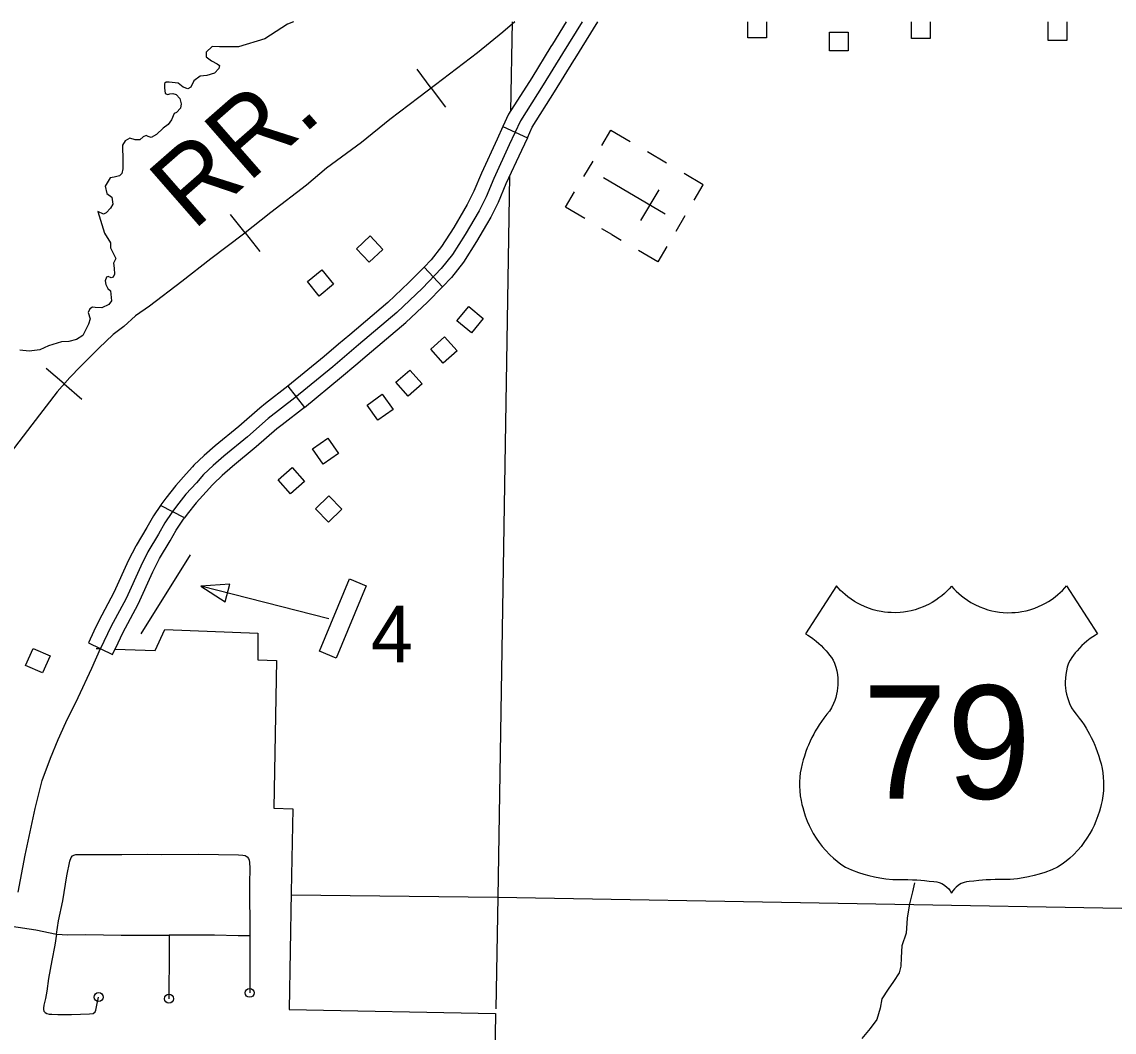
# Model space of a CAD drawing. Extents: x 61396 to 64680, y 55472 to 57605.
# Drawn here: x 62867.8 to 63058.6, y 56508.8 to 56685.3 of the extents above; entities that cross this region are included whole.
import ezdxf

# ---------------------------------------------------------------- set-up
doc = ezdxf.new("R2010")
doc.units = 0
for name, color, linetype in [('22', 7, 'Continuous'), ('31', 7, 'Continuous'), ('33', 7, 'Continuous'), ('35', 7, 'Continuous'), ('4', 7, 'Continuous'), ('40', 7, 'Continuous'), ('5', 7, 'Continuous'), ('56', 7, 'Continuous'), ('57', 7, 'Continuous'), ('6', 7, 'Continuous')]:
    doc.layers.add(name, color=color, linetype=linetype)

msp = doc.modelspace()

# ---------------------------------------------------------------- linework, layer by layer
at = {"layer": '22'}
for points in [[(63030.23, 56586.68), (63029.82, 56586.22), (63029.42, 56585.82), (63028.98, 56585.4), (63028.5, 56584.99), (63028.03, 56584.63), (63027.47, 56584.23), (63026.86, 56583.85), (63026.17, 56583.47), (63025.29, 56583.07), (63024.62, 56582.81), (63023.86, 56582.56), (63023.17, 56582.38), (63022.53, 56582.25), (63021.85, 56582.14), (63021.23, 56582.08), (63020.38, 56582.04), (63019.69, 56582.05), (63019.09, 56582.09), (63018.52, 56582.15), (63017.94, 56582.23), (63017.21, 56582.38), (63016.53, 56582.56), (63015.71, 56582.83), (63015.01, 56583.1), (63014.38, 56583.39), (63013.8, 56583.69), (63013.27, 56584.01), (63012.67, 56584.4), (63012.12, 56584.8), (63011.65, 56585.19), (63011.25, 56585.54), (63010.84, 56585.94), (63010.44, 56586.36), (63010.12, 56586.73), (63004.71, 56578.36), (63005.1, 56578.13), (63005.56, 56577.83), (63005.99, 56577.52), (63006.57, 56577.07), (63007.04, 56576.67), (63007.45, 56576.29), (63007.87, 56575.86), (63008.3, 56575.38), (63008.61, 56575.01), (63008.91, 56574.62), (63009.22, 56574.19), (63009.52, 56573.74), (63009.79, 56573.21), (63010, 56572.55), (63010.16, 56571.91), (63010.28, 56571.22), (63010.35, 56570.58), (63010.37, 56569.96), (63010.35, 56569.38), (63010.32, 56568.91), (63010.24, 56568.34), (63010.13, 56567.81), (63009.98, 56567.23), (63009.82, 56566.72), (63009.6, 56566.15), (63009.24, 56565.41), (63008.88, 56564.83), (63008.45, 56564.31), (63007.92, 56563.63), (63007.49, 56563.03), (63007.09, 56562.44), (63006.72, 56561.85), (63006.41, 56561.33), (63006.14, 56560.84), (63005.84, 56560.25), (63005.51, 56559.57), (63005.21, 56558.9), (63005.01, 56558.41), (63004.77, 56557.77), (63004.51, 56556.99), (63004.3, 56556.34), (63004.1, 56555.64), (63003.92, 56554.81), (63003.8, 56554.08), (63003.72, 56553.32), (63003.67, 56552.49), (63003.66, 56551.71), (63003.7, 56550.94), (63003.79, 56550.05), (63003.93, 56549.2), (63004.07, 56548.55), (63004.22, 56547.99), (63004.4, 56547.35), (63004.65, 56546.55), (63005.01, 56545.59), (63005.32, 56544.88), (63005.67, 56544.15), (63006.06, 56543.44), (63006.57, 56542.62), (63007.1, 56541.86), (63007.61, 56541.2), (63008.19, 56540.53), (63008.94, 56539.75), (63009.57, 56539.17), (63010.22, 56538.62)], [(63030.23, 56586.68), (63030.64, 56586.22), (63031.03, 56585.82), (63031.48, 56585.4), (63031.96, 56584.99), (63032.43, 56584.63), (63032.99, 56584.23), (63033.6, 56583.85), (63034.29, 56583.47), (63035.16, 56583.07), (63035.83, 56582.81), (63036.59, 56582.56), (63037.29, 56582.38), (63037.93, 56582.25), (63038.6, 56582.14), (63039.22, 56582.08), (63040.07, 56582.04), (63040.76, 56582.05), (63041.37, 56582.09), (63041.94, 56582.15), (63042.52, 56582.23), (63043.25, 56582.38), (63043.92, 56582.56), (63044.75, 56582.83), (63045.44, 56583.1), (63046.07, 56583.39), (63046.65, 56583.69), (63047.19, 56584.01), (63047.79, 56584.4), (63048.34, 56584.8), (63048.81, 56585.19), (63049.21, 56585.54), (63049.61, 56585.94), (63050.01, 56586.36), (63050.34, 56586.73), (63055.74, 56578.36), (63055.36, 56578.13), (63054.9, 56577.83), (63054.46, 56577.52), (63053.88, 56577.07), (63053.42, 56576.67), (63053.01, 56576.29), (63052.59, 56575.86), (63052.16, 56575.38), (63051.85, 56575.01), (63051.55, 56574.62), (63051.24, 56574.19), (63050.94, 56573.74), (63050.66, 56573.21), (63050.45, 56572.55), (63050.29, 56571.91), (63050.17, 56571.22), (63050.11, 56570.58), (63050.09, 56569.96), (63050.1, 56569.38), (63050.14, 56568.91), (63050.22, 56568.34), (63050.32, 56567.81), (63050.47, 56567.23), (63050.64, 56566.72), (63050.86, 56566.15), (63051.21, 56565.41), (63051.57, 56564.83), (63052.01, 56564.31), (63052.54, 56563.63), (63052.97, 56563.03), (63053.37, 56562.44), (63053.73, 56561.85), (63054.04, 56561.33), (63054.32, 56560.84), (63054.62, 56560.25), (63054.95, 56559.57), (63055.24, 56558.9), (63055.44, 56558.41), (63055.68, 56557.77), (63055.95, 56556.99), (63056.16, 56556.34), (63056.35, 56555.64), (63056.53, 56554.81), (63056.65, 56554.08), (63056.74, 56553.32), (63056.79, 56552.49), (63056.79, 56551.71), (63056.76, 56550.94), (63056.67, 56550.05), (63056.53, 56549.2), (63056.39, 56548.55), (63056.24, 56547.99), (63056.05, 56547.35), (63055.81, 56546.55), (63055.45, 56545.59), (63055.14, 56544.88), (63054.78, 56544.15), (63054.39, 56543.44), (63053.88, 56542.62), (63053.36, 56541.86), (63052.85, 56541.2), (63052.27, 56540.53), (63051.52, 56539.75), (63050.89, 56539.17), (63050.23, 56538.62)], [(63010.22, 56538.62), (63010.9, 56538.11), (63011.72, 56537.57), (63012.74, 56537.12), (63013.94, 56536.66), (63014.92, 56536.34), (63015.79, 56536.1), (63016.79, 56535.87), (63017.72, 56535.69), (63018.73, 56535.56), (63019.99, 56535.45), (63020.96, 56535.41), (63021.79, 56535.42), (63022.59, 56535.41), (63023.4, 56535.38), (63024.16, 56535.35), (63024.83, 56535.3), (63025.48, 56535.25), (63026.33, 56535.16), (63027.15, 56535.06), (63027.64, 56534.99), (63028.05, 56534.91), (63028.54, 56534.7), (63028.82, 56534.55), (63029.07, 56534.38), (63029.4, 56534.11), (63029.73, 56533.79), (63029.99, 56533.45), (63030.23, 56533.06)], [(63050.23, 56538.62), (63049.55, 56538.11), (63048.74, 56537.57), (63047.72, 56537.12), (63046.52, 56536.66), (63045.54, 56536.34), (63044.66, 56536.1), (63043.67, 56535.87), (63042.73, 56535.69), (63041.73, 56535.56), (63040.46, 56535.45), (63039.5, 56535.41), (63038.67, 56535.42), (63037.86, 56535.41), (63037.06, 56535.38), (63036.29, 56535.35), (63035.63, 56535.3), (63034.97, 56535.25), (63034.13, 56535.16), (63033.31, 56535.06), (63032.82, 56534.99), (63032.41, 56534.91), (63031.92, 56534.7), (63031.64, 56534.55), (63031.39, 56534.38), (63031.05, 56534.11), (63030.73, 56533.79), (63030.47, 56533.45), (63030.23, 56533.06)]]:
    msp.add_lwpolyline(points, dxfattribs=at)
at = {"layer": '31'}
for p, q in [((62951.83, 56666.98), (62956.1, 56665.03)), ((62956.1, 56665.03), (62956.1, 56665.03)), ((62941.27, 56638.99), (62938.05, 56642.41)), ((62926.13, 56625.35), (62926.13, 56625.35)), ((62914.27, 56621.62), (62917.15, 56617.92)), ((62896.21, 56598.61), (62891.99, 56600.75)), ((62891.85, 56591.53), (62891.85, 56591.52))]:
    msp.add_line(p, q, dxfattribs=at)
for points in [[(62965.67, 56685.27), (62962.22, 56679.74), (62958.85, 56674.26), (62954.88, 56668), (62952.95, 56663.79), (62950.22, 56657.91), (62948.89, 56654.7), (62947.67, 56652.26), (62945.23, 56648.12), (62943.01, 56644.65), (62941.05, 56642.17), (62937.8, 56638.73), (62933.31, 56634.51), (62926.61, 56628.82), (62922.1, 56625.02), (62915.46, 56619.58), (62910.84, 56615.98), (62907.21, 56612.77), (62903.08, 56609.37), (62901.19, 56607.76), (62899.54, 56606.17), (62898.26, 56604.72), (62896.44, 56602.74), (62894.79, 56600.66), (62893.99, 56599.53), (62892.77, 56597.72), (62891.65, 56595.77), (62889.8, 56592.67), (62888.54, 56590.19), (62885.97, 56584.54), (62883.33, 56579.56), (62881.5, 56575.76)], [(62962.9, 56685.27), (62960.47, 56681.37)], [(62964.45, 56678.89), (62968.43, 56685.27)], [(62960.47, 56681.37), (62960.23, 56680.98), (62956.87, 56675.5), (62952.81, 56669.12), (62951.83, 56666.98)], [(62956.1, 56665.03), (62956.94, 56666.88), (62960.84, 56673.02), (62964.21, 56678.51), (62964.45, 56678.89)], [(62951.83, 56666.98), (62950.82, 56664.77), (62948.07, 56658.86), (62946.75, 56655.67), (62945.61, 56653.38), (62944.95, 56652.26)], [(62956.1, 56665.03), (62955.08, 56662.81), (62952.36, 56656.97), (62951.02, 56653.72), (62949.73, 56651.14), (62948.99, 56649.88)], [(62944.95, 56652.26), (62943.23, 56649.35), (62941.1, 56646.01), (62939.28, 56643.71), (62938.05, 56642.41)], [(62948.99, 56649.88), (62947.22, 56646.89), (62944.92, 56643.28), (62942.82, 56640.63), (62941.27, 56638.99)], [(62938.05, 56642.41), (62935.42, 56639.71), (62931.75, 56636.26), (62925.1, 56630.61), (62923.11, 56628.93)], [(62926.13, 56625.35), (62928.13, 56627.03), (62934.87, 56632.76), (62938.63, 56636.3), (62941.27, 56638.99)], [(62923.11, 56628.93), (62920.6, 56626.83), (62914.27, 56621.62)], [(62917.15, 56617.92), (62923.6, 56623.22), (62926.13, 56625.35)], [(62914.27, 56621.62), (62910.37, 56618.58)], [(62910.37, 56618.58), (62909.34, 56617.78), (62905.69, 56614.56), (62901.57, 56611.17), (62899.62, 56609.49), (62897.85, 56607.8), (62897.59, 56607.5)], [(62917.15, 56617.92), (62913.25, 56614.89)], [(62913.25, 56614.89), (62912.34, 56614.17), (62908.73, 56610.99), (62904.59, 56607.58), (62902.77, 56606.02), (62901.23, 56604.54), (62901.1, 56604.39)], [(62897.59, 56607.5), (62896.51, 56606.29), (62894.65, 56604.26), (62892.91, 56602.06), (62892.06, 56600.86), (62891.99, 56600.75)], [(62901.1, 56604.39), (62900, 56603.15), (62898.22, 56601.21), (62896.66, 56599.25), (62896.21, 56598.61)], [(62891.99, 56600.75), (62890.78, 56598.96), (62889.63, 56596.95), (62887.75, 56593.8), (62887.67, 56593.64)], [(62891.85, 56591.52), (62891.85, 56591.53), (62893.67, 56594.58), (62894.76, 56596.48), (62895.92, 56598.2), (62896.21, 56598.61)], [(62887.67, 56593.64), (62886.43, 56591.21), (62883.87, 56585.58), (62881.23, 56580.61), (62880.36, 56578.8)], [(62884.58, 56576.77), (62885.42, 56578.5), (62888.07, 56583.51), (62890.66, 56589.17), (62891.85, 56591.53)], [(62880.36, 56578.8), (62879.39, 56576.78), (62883.61, 56574.74)], [(62883.61, 56574.74), (62884.58, 56576.77)]]:
    msp.add_lwpolyline(points, dxfattribs=at)
at = {"layer": '33'}
for points in [[(62867.12, 56533.22), (62868.33, 56539.7), (62870.08, 56547.82), (62871.34, 56552.74), (62872.79, 56556.64), (62874.14, 56559.88), (62875.47, 56562.88), (62877.61, 56567.24), (62880.02, 56572.36), (62881.5, 56575.76)], [(62873.82, 56525.9), (62874.17, 56528.19), (62874.94, 56531.68), (62875.65, 56536.09), (62876.16, 56538.62), (62876.38, 56539.28), (62876.61, 56539.54), (62876.85, 56539.69), (62877.21, 56539.77), (62878.49, 56539.77), (62881.45, 56539.82), (62885.25, 56539.77), (62889.75, 56539.86), (62892.1, 56539.79), (62898.64, 56539.84), (62905.64, 56539.75), (62906.41, 56539.69), (62906.78, 56539.59), (62907.14, 56539.36), (62907.37, 56539.08), (62907.52, 56538.78), (62907.57, 56538.41), (62907.61, 56537.43), (62907.56, 56534.75), (62907.58, 56525.6)], [(62865.94, 56527.28), (62870.2, 56526.64), (62873.82, 56525.9)], [(62873.82, 56525.9), (62873.52, 56523.98), (62872.98, 56521.25), (62872.44, 56518.14), (62872.14, 56515.9), (62871.9, 56514.61), (62871.6, 56513.48), (62871.57, 56512.94), (62871.54, 56512.7), (62871.63, 56512.43), (62871.87, 56512.19), (62872.11, 56512.04), (62872.56, 56511.89), (62873.01, 56511.89), (62874.06, 56511.86), (62876.45, 56511.86), (62879.59, 56511.95), (62880.22, 56512.01), (62880.58, 56512.28), (62880.7, 56512.61), (62880.79, 56513.15), (62881.18, 56514.88)], [(62873.82, 56525.9), (62875.81, 56525.75), (62878.97, 56525.82), (62885.13, 56525.71), (62888.48, 56525.67), (62893.51, 56525.67)], [(62893.51, 56525.67), (62893.49, 56523.97), (62893.51, 56520.35), (62893.45, 56517.21), (62893.47, 56514.6)], [(62907.58, 56525.6), (62905.54, 56525.56), (62901.42, 56525.69), (62893.51, 56525.67)], [(62907.58, 56525.6), (62907.58, 56523.05), (62907.61, 56520.93), (62907.58, 56518.13), (62907.58, 56515.62)]]:
    msp.add_lwpolyline(points, dxfattribs=at)
for centre in [(62907.58, 56515.62), (62881.18, 56514.88), (62893.47, 56514.6)]:
    msp.add_circle(centre, 0.781, dxfattribs=at)
at = {"layer": '35'}
for points in [[(62915.21, 56685.27), (62914.21, 56684.89), (62910.21, 56682.29), (62905.6, 56680.89)], [(62905.6, 56680.89), (62902.3, 56680.89), (62901, 56680.94), (62899.97, 56679.96), (62899.97, 56679.17), (62900.9, 56678.47), (62901.88, 56677.92), (62902.3, 56677.64), (62902.21, 56677.12), (62901.42, 56676.33), (62900.11, 56675.87), (62898.95, 56675.78), (62897.8, 56674.94), (62897.3, 56673.83), (62896.8, 56673.56), (62895.96, 56673.83), (62895.08, 56674.56), (62893.49, 56674.75)], [(62893.49, 56674.75), (62893.01, 56674.75), (62892.72, 56674.51), (62892.67, 56673.75)], [(62892.67, 56673.75), (62892.82, 56672.77), (62893.27, 56672.58), (62893.65, 56672.7), (62894.18, 56672.77), (62894.73, 56672.58), (62895.39, 56671.88), (62895.61, 56670.97), (62895.5, 56670.17), (62894.81, 56669.44), (62894.41, 56669.26), (62893.9, 56668.16), (62893.35, 56667.36), (62892.48, 56666.67), (62891.31, 56665.61), (62890.34, 56665.07), (62889.85, 56665.25), (62889.52, 56665.43), (62888.94, 56665.21), (62888.36, 56664.63), (62887.56, 56664.63), (62886.61, 56664.92), (62885.82, 56664.47), (62885.37, 56663.72), (62885.43, 56661.01), (62885.4, 56659.6), (62885.24, 56658.79), (62884.82, 56658.37), (62883.89, 56658.16), (62883.21, 56658.03), (62882.35, 56656.54), (62882.63, 56655.29), (62883.47, 56654.64), (62883.68, 56653.44), (62883.26, 56652.71), (62882.48, 56651.93), (62882.01, 56651.69), (62881.07, 56652.16), (62882.22, 56648.35), (62883.28, 56646.64), (62883.28, 56645.81)], [(62883.28, 56645.81), (62884.19, 56643.9), (62883.77, 56643.08), (62883.92, 56642.23), (62883.94, 56641.2), (62883.71, 56640.65), (62883.38, 56640.56), (62882.85, 56640.77), (62882.54, 56640.65), (62882.33, 56640.01), (62882.44, 56639.37), (62882.81, 56638.71), (62883.28, 56638.26), (62883.44, 56636.55), (62882.97, 56635.89), (62881.76, 56635.29), (62880.58, 56635.36), (62880.13, 56635.4), (62879.66, 56635.13), (62879.37, 56634.49), (62879.68, 56633.36), (62879.43, 56632.45), (62878.42, 56630.46), (62877.34, 56629.76), (62875.97, 56629.44), (62874.69, 56629.39), (62872.42, 56628.68), (62870.9, 56627.94), (62869.06, 56627.76), (62867.4, 56627.9)], [(63023.77, 56534.82), (63023.39, 56533.27), (63022.9, 56531.15), (63022.49, 56528.64), (63022.27, 56526.03), (63021.56, 56523.81), (63021.44, 56521.77), (63021.37, 56520.27), (63021.07, 56519.1), (63020.09, 56517.63), (63019.14, 56516.25), (63018.07, 56514.55), (63017.75, 56512.94), (63017.14, 56510.98), (63016.03, 56509.41), (63014.57, 56507.67)]]:
    msp.add_lwpolyline(points, dxfattribs=at)
at = {"layer": '4'}
for points in [[(62953.42, 56685.27), (62953.17, 56669.68)], [(62952.98, 56658.3), (62950.94, 56532.34), (62950.57, 56512.82)]]:
    msp.add_lwpolyline(points, dxfattribs=at)
at = {"layer": '40'}
for p, q in [((62939.32, 56673.7), (62936.86, 56677.02)), ((62939.32, 56673.7), (62941.78, 56670.39)), ((62906.77, 56648.38), (62904.2, 56651.61)), ((62906.77, 56648.38), (62909.34, 56645.15)), ((62875.15, 56622.03), (62872.04, 56624.73)), ((62875.15, 56622.03), (62878.27, 56619.32))]:
    msp.add_line(p, q, dxfattribs=at)
msp.add_lwpolyline([(62953.89, 56685.27), (62951.79, 56683.48), (62947.4, 56679.86), (62940.06, 56674.26), (62937.11, 56672.07), (62932.09, 56668.2), (62927.13, 56664.18), (62921.01, 56659.68), (62917.5, 56656.73), (62911.26, 56651.95), (62906.51, 56648.17), (62900.82, 56643.85), (62895.74, 56639.89), (62890.07, 56635.57), (62887.64, 56633.9), (62885.6, 56632.07), (62883.74, 56630.64), (62881.21, 56628.27), (62878.02, 56625.07), (62876.13, 56623.15), (62873.94, 56620.63), (62869.52, 56614.87), (62865.75, 56609.91)], dxfattribs=at)
msp.add_lwpolyline([(62953.89, 56685.27), (62951.79, 56683.48), (62947.4, 56679.86), (62940.06, 56674.26), (62937.11, 56672.07), (62932.09, 56668.2), (62927.13, 56664.18), (62921.01, 56659.68), (62917.5, 56656.73), (62911.26, 56651.95), (62906.51, 56648.17), (62900.82, 56643.85), (62895.74, 56639.89), (62890.07, 56635.57), (62887.64, 56633.9), (62885.6, 56632.07), (62883.74, 56630.64), (62881.21, 56628.27), (62878.02, 56625.07), (62876.13, 56623.15), (62873.94, 56620.63), (62869.52, 56614.87), (62865.75, 56609.91)], dxfattribs=at)
at = {"layer": '5'}
for points in [[(62914.84, 56532.75), (62950.94, 56532.34)], [(62950.94, 56532.34), (63069.91, 56530.27)]]:
    msp.add_lwpolyline(points, dxfattribs=at)
at = {"layer": '56'}
for points in [[(62997.89, 56685.27), (62997.89, 56682.5), (62994.62, 56682.5), (62994.62, 56685.27)], [(63026.49, 56685.27), (63026.49, 56682.37), (63023.23, 56682.37), (63023.23, 56685.27)], [(63050.37, 56685.27), (63050.37, 56682.04), (63047.11, 56682.04), (63047.11, 56685.27)], [(62897.18, 56592.15), (62888.57, 56578.33)], [(62921.39, 56580.99), (62899.07, 56586.66)]]:
    msp.add_lwpolyline(points, dxfattribs=at)
for points in [[(63008.89, 56680.19), (63008.89, 56683.44), (63012.15, 56683.44), (63012.15, 56680.19)], [(62928.47, 56643.27), (62926.24, 56645.63), (62928.61, 56647.87), (62930.85, 56645.51)], [(62917.66, 56639.89), (62920.18, 56641.95), (62922.25, 56639.42), (62919.73, 56637.36)], [(62943.8, 56633.01), (62945.86, 56635.52), (62948.39, 56633.46), (62946.33, 56630.94)], [(62939.22, 56628.06), (62941.63, 56630.24), (62943.82, 56627.82), (62941.41, 56625.64)], [(62935.28, 56619.85), (62933.14, 56622.29), (62935.59, 56624.44), (62937.74, 56622)], [(62929.99, 56615.66), (62928.09, 56618.31), (62930.75, 56620.2), (62932.64, 56617.56)], [(62918.55, 56610.68), (62921.22, 56612.54), (62923.08, 56609.85), (62920.41, 56608)], [(62912.57, 56605.25), (62915, 56607.41), (62917.16, 56604.97), (62914.73, 56602.81)], [(62919.11, 56600.18), (62921.44, 56602.45), (62923.71, 56600.1), (62921.38, 56597.84)], [(62903.31, 56583.94), (62904.09, 56587.02), (62899.07, 56586.66)], [(62925.03, 56587.95), (62927.92, 56586.75), (62922.69, 56574.12), (62919.8, 56575.32)], [(62868.42, 56572.84), (62869.74, 56575.81), (62872.72, 56574.49), (62871.4, 56571.51)]]:
    msp.add_lwpolyline(points, close=True, dxfattribs=at)
at = {"layer": '57'}
for p, q in [((62980.43, 56660.6), (62977.07, 56662.58)), ((62967.52, 56660.94), (62965.93, 56658.24)), ((62980.19, 56651.67), (62969.42, 56658.02)), ((62979.09, 56655.95), (62975.9, 56650.54)), ((62974.81, 56654.84), (62974.81, 56654.84)), ((62974.81, 56654.84), (62974.81, 56654.84)), ((62982.08, 56648.72), (62983.67, 56651.41)), ((62970.84, 56648.11), (62969.13, 56649.12)), ((62970.84, 56648.11), (62972.5, 56647.14))]:
    msp.add_line(p, q, dxfattribs=at)
for points in [[(62969.11, 56663.64), (62970.7, 56666.33), (62974.07, 56664.35)], [(62985.26, 56654.12), (62986.85, 56656.81), (62983.49, 56658.8)], [(62966.13, 56650.89), (62962.76, 56652.88), (62964.35, 56655.57)], [(62980.5, 56646.04), (62978.92, 56643.35), (62975.55, 56645.34)]]:
    msp.add_lwpolyline(points, dxfattribs=at)
at = {"layer": '6'}
for p, q in [((62914.84, 56533.19), (62914.49, 56512.69)), ((62914.49, 56512.69), (62950.56, 56511.99)), ((62950.56, 56511.99), (62950.17, 56491.2))]:
    msp.add_line(p, q, dxfattribs=at)
for points in [[(62884.09, 56575.67), (62891.04, 56575.43), (62892.75, 56579.08), (62909.03, 56578.48), (62908.99, 56573.82)], [(62880.76, 56575.79), (62881.46, 56575.76)], [(62908.99, 56573.82), (62912.27, 56573.7), (62911.82, 56547.86), (62915.1, 56547.75), (62914.84, 56533.19)]]:
    msp.add_lwpolyline(points, dxfattribs=at)

# ---------------------------------------------------------------- texts
at = {"layer": '22'}
msp.add_text('79', height=19.8, dxfattribs=at).set_placement((63014.67, 56549.53))
at = {"layer": '40'}
msp.add_text('RR.', height=13.2, rotation=41.1816, dxfattribs=at).set_placement((62897.69, 56648.64))
at = {"layer": '56'}
msp.add_text('4', height=9.9, dxfattribs=at).set_placement((62928.75, 56573.37))

doc.saveas('drawing.dxf')
